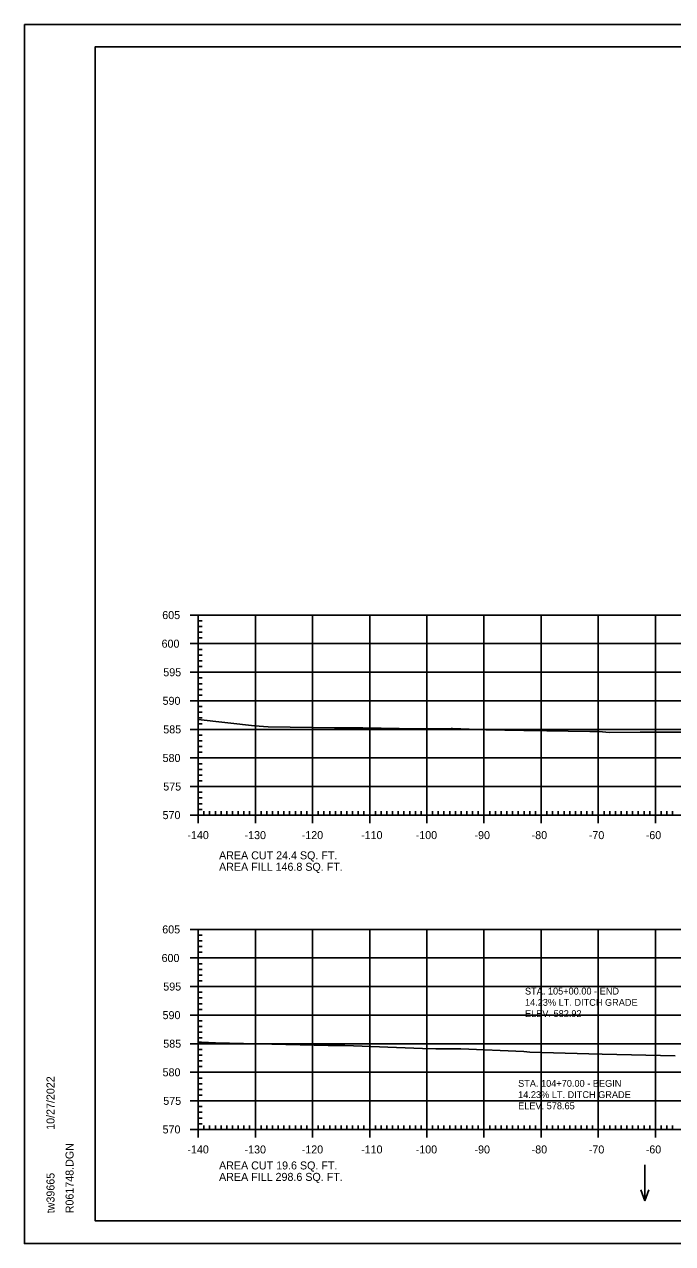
# Model space of a CAD drawing. Extents: x 961436 to 1372525, y 380079 to 2027791.
# Drawn here: x 1371024.5 to 1371137.9, y 380535.8 to 380749.1 of the extents above; entities that cross this region are included whole.
import ezdxf

# ---------------------------------------------------------------- set-up
doc = ezdxf.new("R2010")
doc.units = 0
for name, color, linetype in [('R_Axis', 7, 'Continuous'), ('R_Axis Annot', 7, 'Continuous'), ('R_Border', 7, 'Continuous'), ('R_Exist Surface', 7, 'Continuous'), ('R_Fin Surface Annot', 7, 'Continuous'), ('R_Grid', 7, 'Continuous'), ('R_No Plot', 7, 'Continuous'), ('R_Water Annot', 7, 'Continuous')]:
    doc.layers.add(name, color=color, linetype=linetype)

msp = doc.modelspace()

# ---------------------------------------------------------------- linework, layer by layer
at = {"layer": 'R_Axis'}
for p, q in [((1371053.48, 380645.73), (1371056.28, 380645.73)), ((1371054.88, 380610.73), (1371054.88, 380645.73)), ((1371054.88, 380644.73), (1371055.58, 380644.73)), ((1371054.88, 380643.73), (1371055.58, 380643.73)), ((1371054.88, 380642.73), (1371055.58, 380642.73)), ((1371054.88, 380641.73), (1371055.58, 380641.73)), ((1371053.48, 380640.73), (1371056.28, 380640.73)), ((1371054.88, 380639.73), (1371055.58, 380639.73)), ((1371054.88, 380638.73), (1371055.58, 380638.73)), ((1371054.88, 380637.73), (1371055.58, 380637.73)), ((1371053.48, 380635.73), (1371056.28, 380635.73)), ((1371054.88, 380636.73), (1371055.58, 380636.73)), ((1371054.88, 380634.73), (1371055.58, 380634.73)), ((1371054.88, 380633.73), (1371055.58, 380633.73)), ((1371054.88, 380632.73), (1371055.58, 380632.73)), ((1371053.48, 380630.73), (1371056.28, 380630.73)), ((1371054.88, 380631.73), (1371055.58, 380631.73)), ((1371054.88, 380629.73), (1371055.58, 380629.73)), ((1371054.88, 380628.73), (1371055.58, 380628.73)), ((1371054.88, 380627.73), (1371055.58, 380627.73)), ((1371054.88, 380626.73), (1371055.58, 380626.73)), ((1371053.48, 380625.73), (1371056.28, 380625.73)), ((1371054.88, 380624.73), (1371055.58, 380624.73)), ((1371054.88, 380623.73), (1371055.58, 380623.73)), ((1371054.88, 380622.73), (1371055.58, 380622.73)), ((1371053.48, 380620.73), (1371056.28, 380620.73)), ((1371054.88, 380621.73), (1371055.58, 380621.73)), ((1371054.88, 380619.73), (1371055.58, 380619.73)), ((1371054.88, 380618.73), (1371055.58, 380618.73)), ((1371053.48, 380615.73), (1371056.28, 380615.73)), ((1371054.88, 380617.73), (1371055.58, 380617.73)), ((1371054.88, 380616.73), (1371055.58, 380616.73)), ((1371054.88, 380614.73), (1371055.58, 380614.73)), ((1371054.88, 380613.73), (1371055.58, 380613.73)), ((1371054.88, 380612.73), (1371055.58, 380612.73)), ((1371054.88, 380609.33), (1371054.88, 380612.13)), ((1371054.88, 380611.73), (1371055.58, 380611.73)), ((1371055.88, 380610.73), (1371055.88, 380611.43)), ((1371056.88, 380610.73), (1371056.88, 380611.43)), ((1371057.88, 380610.73), (1371057.88, 380611.43)), ((1371058.88, 380610.73), (1371058.88, 380611.43)), ((1371059.88, 380610.73), (1371059.88, 380611.43)), ((1371060.88, 380610.73), (1371060.88, 380611.43)), ((1371061.88, 380610.73), (1371061.88, 380611.43)), ((1371062.88, 380610.73), (1371062.88, 380611.43)), ((1371063.88, 380610.73), (1371063.88, 380611.43)), ((1371064.88, 380609.33), (1371064.88, 380612.13)), ((1371065.88, 380610.73), (1371065.88, 380611.43)), ((1371066.88, 380610.73), (1371066.88, 380611.43)), ((1371067.88, 380610.73), (1371067.88, 380611.43)), ((1371068.88, 380610.73), (1371068.88, 380611.43)), ((1371069.88, 380610.73), (1371069.88, 380611.43)), ((1371070.88, 380610.73), (1371070.88, 380611.43)), ((1371071.88, 380610.73), (1371071.88, 380611.43)), ((1371072.88, 380610.73), (1371072.88, 380611.43)), ((1371073.88, 380610.73), (1371073.88, 380611.43)), ((1371074.88, 380609.33), (1371074.88, 380612.13)), ((1371075.88, 380610.73), (1371075.88, 380611.43)), ((1371076.88, 380610.73), (1371076.88, 380611.43)), ((1371077.88, 380610.73), (1371077.88, 380611.43)), ((1371078.88, 380610.73), (1371078.88, 380611.43)), ((1371079.88, 380610.73), (1371079.88, 380611.43)), ((1371080.88, 380610.73), (1371080.88, 380611.43)), ((1371081.88, 380610.73), (1371081.88, 380611.43)), ((1371082.88, 380610.73), (1371082.88, 380611.43)), ((1371083.88, 380610.73), (1371083.88, 380611.43)), ((1371084.88, 380609.33), (1371084.88, 380612.13)), ((1371085.88, 380610.73), (1371085.88, 380611.43)), ((1371086.88, 380610.73), (1371086.88, 380611.43)), ((1371087.88, 380610.73), (1371087.88, 380611.43)), ((1371088.88, 380610.73), (1371088.88, 380611.43)), ((1371089.88, 380610.73), (1371089.88, 380611.43)), ((1371090.88, 380610.73), (1371090.88, 380611.43)), ((1371091.88, 380610.73), (1371091.88, 380611.43)), ((1371092.88, 380610.73), (1371092.88, 380611.43)), ((1371093.88, 380610.73), (1371093.88, 380611.43)), ((1371094.88, 380609.33), (1371094.88, 380612.13)), ((1371095.88, 380610.73), (1371095.88, 380611.43)), ((1371096.88, 380610.73), (1371096.88, 380611.43)), ((1371097.88, 380610.73), (1371097.88, 380611.43)), ((1371098.88, 380610.73), (1371098.88, 380611.43)), ((1371099.88, 380610.73), (1371099.88, 380611.43)), ((1371100.88, 380610.73), (1371100.88, 380611.43)), ((1371101.88, 380610.73), (1371101.88, 380611.43)), ((1371102.88, 380610.73), (1371102.88, 380611.43)), ((1371103.88, 380610.73), (1371103.88, 380611.43)), ((1371104.88, 380609.33), (1371104.88, 380612.13)), ((1371105.88, 380610.73), (1371105.88, 380611.43)), ((1371106.88, 380610.73), (1371106.88, 380611.43)), ((1371107.88, 380610.73), (1371107.88, 380611.43)), ((1371108.88, 380610.73), (1371108.88, 380611.43)), ((1371109.88, 380610.73), (1371109.88, 380611.43)), ((1371110.88, 380610.73), (1371110.88, 380611.43)), ((1371111.88, 380610.73), (1371111.88, 380611.43)), ((1371112.88, 380610.73), (1371112.88, 380611.43)), ((1371113.88, 380610.73), (1371113.88, 380611.43)), ((1371114.88, 380609.33), (1371114.88, 380612.13)), ((1371115.88, 380610.73), (1371115.88, 380611.43)), ((1371116.88, 380610.73), (1371116.88, 380611.43)), ((1371117.88, 380610.73), (1371117.88, 380611.43)), ((1371118.88, 380610.73), (1371118.88, 380611.43)), ((1371119.88, 380610.73), (1371119.88, 380611.43)), ((1371120.88, 380610.73), (1371120.88, 380611.43)), ((1371121.88, 380610.73), (1371121.88, 380611.43)), ((1371122.88, 380610.73), (1371122.88, 380611.43)), ((1371123.88, 380610.73), (1371123.88, 380611.43)), ((1371124.88, 380609.33), (1371124.88, 380612.13)), ((1371125.88, 380610.73), (1371125.88, 380611.43)), ((1371126.88, 380610.73), (1371126.88, 380611.43)), ((1371127.88, 380610.73), (1371127.88, 380611.43)), ((1371128.88, 380610.73), (1371128.88, 380611.43)), ((1371129.88, 380610.73), (1371129.88, 380611.43)), ((1371130.88, 380610.73), (1371130.88, 380611.43)), ((1371131.88, 380610.73), (1371131.88, 380611.43)), ((1371132.88, 380610.73), (1371132.88, 380611.43)), ((1371133.88, 380610.73), (1371133.88, 380611.43)), ((1371134.88, 380609.33), (1371134.88, 380612.13)), ((1371135.88, 380610.73), (1371135.88, 380611.43)), ((1371136.88, 380610.73), (1371136.88, 380611.43)), ((1371137.88, 380610.73), (1371137.88, 380611.43)), ((1371053.48, 380610.73), (1371056.28, 380610.73)), ((1371054.88, 380610.73), (1371334.88, 380610.73)), ((1371053.48, 380590.73), (1371056.28, 380590.73)), ((1371054.88, 380555.73), (1371054.88, 380590.73)), ((1371054.88, 380589.73), (1371055.58, 380589.73)), ((1371054.88, 380588.73), (1371055.58, 380588.73)), ((1371054.88, 380587.73), (1371055.58, 380587.73)), ((1371054.88, 380586.73), (1371055.58, 380586.73)), ((1371053.48, 380585.73), (1371056.28, 380585.73)), ((1371054.88, 380584.73), (1371055.58, 380584.73)), ((1371054.88, 380583.73), (1371055.58, 380583.73)), ((1371054.88, 380582.73), (1371055.58, 380582.73)), ((1371054.88, 380581.73), (1371055.58, 380581.73)), ((1371053.48, 380580.73), (1371056.28, 380580.73)), ((1371054.88, 380579.73), (1371055.58, 380579.73)), ((1371054.88, 380578.73), (1371055.58, 380578.73)), ((1371054.88, 380577.73), (1371055.58, 380577.73)), ((1371053.48, 380575.73), (1371056.28, 380575.73)), ((1371054.88, 380576.73), (1371055.58, 380576.73)), ((1371054.88, 380574.73), (1371055.58, 380574.73)), ((1371054.88, 380573.73), (1371055.58, 380573.73)), ((1371054.88, 380572.73), (1371055.58, 380572.73)), ((1371054.88, 380571.73), (1371055.58, 380571.73)), ((1371053.48, 380570.73), (1371056.28, 380570.73)), ((1371054.88, 380569.73), (1371055.58, 380569.73)), ((1371054.88, 380568.73), (1371055.58, 380568.73)), ((1371054.88, 380567.73), (1371055.58, 380567.73)), ((1371054.88, 380566.73), (1371055.58, 380566.73)), ((1371053.48, 380565.73), (1371056.28, 380565.73)), ((1371054.88, 380564.73), (1371055.58, 380564.73)), ((1371054.88, 380563.73), (1371055.58, 380563.73)), ((1371054.88, 380562.73), (1371055.58, 380562.73)), ((1371053.48, 380560.73), (1371056.28, 380560.73)), ((1371054.88, 380561.73), (1371055.58, 380561.73)), ((1371054.88, 380559.73), (1371055.58, 380559.73)), ((1371054.88, 380558.73), (1371055.58, 380558.73)), ((1371054.88, 380557.73), (1371055.58, 380557.73)), ((1371054.88, 380554.33), (1371054.88, 380557.13)), ((1371054.88, 380556.73), (1371055.58, 380556.73)), ((1371055.88, 380555.73), (1371055.88, 380556.43)), ((1371056.88, 380555.73), (1371056.88, 380556.43)), ((1371057.88, 380555.73), (1371057.88, 380556.43)), ((1371058.88, 380555.73), (1371058.88, 380556.43)), ((1371059.88, 380555.73), (1371059.88, 380556.43)), ((1371060.88, 380555.73), (1371060.88, 380556.43)), ((1371061.88, 380555.73), (1371061.88, 380556.43)), ((1371062.88, 380555.73), (1371062.88, 380556.43)), ((1371063.88, 380555.73), (1371063.88, 380556.43)), ((1371064.88, 380554.33), (1371064.88, 380557.13)), ((1371065.88, 380555.73), (1371065.88, 380556.43)), ((1371066.88, 380555.73), (1371066.88, 380556.43)), ((1371067.88, 380555.73), (1371067.88, 380556.43)), ((1371068.88, 380555.73), (1371068.88, 380556.43)), ((1371069.88, 380555.73), (1371069.88, 380556.43)), ((1371070.88, 380555.73), (1371070.88, 380556.43)), ((1371071.88, 380555.73), (1371071.88, 380556.43)), ((1371072.88, 380555.73), (1371072.88, 380556.43)), ((1371073.88, 380555.73), (1371073.88, 380556.43)), ((1371074.88, 380554.33), (1371074.88, 380557.13)), ((1371075.88, 380555.73), (1371075.88, 380556.43)), ((1371076.88, 380555.73), (1371076.88, 380556.43)), ((1371077.88, 380555.73), (1371077.88, 380556.43)), ((1371078.88, 380555.73), (1371078.88, 380556.43)), ((1371079.88, 380555.73), (1371079.88, 380556.43)), ((1371080.88, 380555.73), (1371080.88, 380556.43)), ((1371081.88, 380555.73), (1371081.88, 380556.43)), ((1371082.88, 380555.73), (1371082.88, 380556.43)), ((1371083.88, 380555.73), (1371083.88, 380556.43)), ((1371084.88, 380554.33), (1371084.88, 380557.13)), ((1371085.88, 380555.73), (1371085.88, 380556.43)), ((1371086.88, 380555.73), (1371086.88, 380556.43)), ((1371087.88, 380555.73), (1371087.88, 380556.43)), ((1371088.88, 380555.73), (1371088.88, 380556.43)), ((1371089.88, 380555.73), (1371089.88, 380556.43)), ((1371090.88, 380555.73), (1371090.88, 380556.43)), ((1371091.88, 380555.73), (1371091.88, 380556.43)), ((1371092.88, 380555.73), (1371092.88, 380556.43)), ((1371093.88, 380555.73), (1371093.88, 380556.43)), ((1371094.88, 380554.33), (1371094.88, 380557.13)), ((1371095.88, 380555.73), (1371095.88, 380556.43)), ((1371096.88, 380555.73), (1371096.88, 380556.43)), ((1371097.88, 380555.73), (1371097.88, 380556.43)), ((1371098.88, 380555.73), (1371098.88, 380556.43)), ((1371099.88, 380555.73), (1371099.88, 380556.43)), ((1371100.88, 380555.73), (1371100.88, 380556.43)), ((1371101.88, 380555.73), (1371101.88, 380556.43)), ((1371102.88, 380555.73), (1371102.88, 380556.43)), ((1371103.88, 380555.73), (1371103.88, 380556.43)), ((1371104.88, 380554.33), (1371104.88, 380557.13)), ((1371105.88, 380555.73), (1371105.88, 380556.43)), ((1371106.88, 380555.73), (1371106.88, 380556.43)), ((1371107.88, 380555.73), (1371107.88, 380556.43)), ((1371108.88, 380555.73), (1371108.88, 380556.43)), ((1371109.88, 380555.73), (1371109.88, 380556.43)), ((1371110.88, 380555.73), (1371110.88, 380556.43)), ((1371111.88, 380555.73), (1371111.88, 380556.43)), ((1371112.88, 380555.73), (1371112.88, 380556.43)), ((1371113.88, 380555.73), (1371113.88, 380556.43)), ((1371114.88, 380554.33), (1371114.88, 380557.13)), ((1371115.88, 380555.73), (1371115.88, 380556.43)), ((1371116.88, 380555.73), (1371116.88, 380556.43)), ((1371117.88, 380555.73), (1371117.88, 380556.43)), ((1371118.88, 380555.73), (1371118.88, 380556.43)), ((1371119.88, 380555.73), (1371119.88, 380556.43)), ((1371120.88, 380555.73), (1371120.88, 380556.43)), ((1371121.88, 380555.73), (1371121.88, 380556.43)), ((1371122.88, 380555.73), (1371122.88, 380556.43)), ((1371123.88, 380555.73), (1371123.88, 380556.43)), ((1371124.88, 380554.33), (1371124.88, 380557.13)), ((1371125.88, 380555.73), (1371125.88, 380556.43)), ((1371126.88, 380555.73), (1371126.88, 380556.43)), ((1371127.88, 380555.73), (1371127.88, 380556.43)), ((1371128.88, 380555.73), (1371128.88, 380556.43)), ((1371129.88, 380555.73), (1371129.88, 380556.43)), ((1371130.88, 380555.73), (1371130.88, 380556.43)), ((1371131.88, 380555.73), (1371131.88, 380556.43)), ((1371132.88, 380555.73), (1371132.88, 380556.43)), ((1371133.88, 380555.73), (1371133.88, 380556.43)), ((1371134.88, 380554.33), (1371134.88, 380557.13)), ((1371135.88, 380555.73), (1371135.88, 380556.43)), ((1371136.88, 380555.73), (1371136.88, 380556.43)), ((1371137.88, 380555.73), (1371137.88, 380556.43)), ((1371053.48, 380555.73), (1371056.28, 380555.73)), ((1371054.88, 380555.73), (1371334.88, 380555.73))]:
    msp.add_line(p, q, dxfattribs=at)
at = {"layer": 'R_Border'}
for p, q in [((1371036.88, 380745.19), (1371353.06, 380745.19)), ((1371036.88, 380539.73), (1371036.88, 380745.19)), ((1371036.88, 380539.73), (1371036.88, 380539.73)), ((1371353.06, 380539.73), (1371036.88, 380539.73))]:
    msp.add_line(p, q, dxfattribs=at)
at = {"layer": 'R_Exist Surface'}
for points in [[(1371054.88, 380627.45), (1371064.74, 380626.36), (1371067.12, 380626.17), (1371078.72, 380626.01), (1371083.4, 380625.99), (1371083.7, 380625.98), (1371093.22, 380625.82), (1371099.16, 380625.9), (1371099.34, 380625.88), (1371105.21, 380625.65), (1371111.85, 380625.53), (1371112.09, 380625.54), (1371123.4, 380625.37), (1371125.01, 380625.35), (1371126.8, 380625.21), (1371132.19, 380625.24), (1371140.02, 380625.23)], [(1371054.88, 380571.01), (1371055.44, 380571.01), (1371057.89, 380570.91), (1371077.64, 380570.41), (1371080.54, 380570.41), (1371094.14, 380569.88), (1371096.48, 380569.85), (1371100.8, 380569.82), (1371111.84, 380569.37), (1371112.91, 380569.24), (1371123.21, 380568.98), (1371125.57, 380568.88), (1371138.34, 380568.59)]]:
    msp.add_lwpolyline(points, dxfattribs=at)
at = {"layer": 'R_Grid'}
for p, q in [((1371054.88, 380645.73), (1371334.88, 380645.73)), ((1371054.88, 380610.73), (1371054.88, 380645.73)), ((1371064.88, 380610.73), (1371064.88, 380645.73)), ((1371074.88, 380610.73), (1371074.88, 380645.73)), ((1371084.88, 380610.73), (1371084.88, 380645.73)), ((1371094.88, 380610.73), (1371094.88, 380645.73)), ((1371104.88, 380610.73), (1371104.88, 380645.73)), ((1371114.88, 380610.73), (1371114.88, 380645.73)), ((1371124.88, 380610.73), (1371124.88, 380645.73)), ((1371134.88, 380610.73), (1371134.88, 380645.73)), ((1371054.88, 380640.73), (1371334.88, 380640.73)), ((1371054.88, 380635.73), (1371334.88, 380635.73)), ((1371054.88, 380630.73), (1371334.88, 380630.73)), ((1371054.88, 380625.73), (1371334.88, 380625.73)), ((1371054.88, 380620.73), (1371334.88, 380620.73)), ((1371054.88, 380615.73), (1371334.88, 380615.73)), ((1371054.88, 380610.73), (1371334.88, 380610.73)), ((1371054.88, 380590.73), (1371334.88, 380590.73)), ((1371054.88, 380555.73), (1371054.88, 380590.73)), ((1371064.88, 380555.73), (1371064.88, 380590.73)), ((1371074.88, 380555.73), (1371074.88, 380590.73)), ((1371084.88, 380555.73), (1371084.88, 380590.73)), ((1371094.88, 380555.73), (1371094.88, 380590.73)), ((1371104.88, 380555.73), (1371104.88, 380590.73)), ((1371114.88, 380555.73), (1371114.88, 380590.73)), ((1371124.88, 380555.73), (1371124.88, 380590.73)), ((1371134.88, 380555.73), (1371134.88, 380590.73)), ((1371054.88, 380585.73), (1371334.88, 380585.73)), ((1371054.88, 380580.73), (1371334.88, 380580.73)), ((1371054.88, 380575.73), (1371334.88, 380575.73)), ((1371054.88, 380570.73), (1371334.88, 380570.73)), ((1371054.88, 380565.73), (1371334.88, 380565.73)), ((1371054.88, 380560.73), (1371334.88, 380560.73)), ((1371054.88, 380555.73), (1371334.88, 380555.73))]:
    msp.add_line(p, q, dxfattribs=at)
at = {"layer": 'R_No Plot'}
for p, q in [((1371024.48, 380749.09), (1371357.81, 380749.09)), ((1371024.48, 380535.76), (1371357.81, 380535.76))]:
    msp.add_line(p, q, dxfattribs=at)
for points in [[(1371024.47, 380749.09), (1371357.81, 380749.09), (1371357.81, 380535.75), (1371024.47, 380535.75)], [(1371270.8, 380745.19), (1371290.42, 380745.19), (1371290.42, 380735.31), (1371306.53, 380735.31), (1371329.73, 380735.31), (1371329.85, 380707.16), (1371353.06, 380707.16), (1371353.06, 380539.73), (1371036.88, 380539.73), (1371036.88, 380745.19)]]:
    msp.add_lwpolyline(points, close=True, dxfattribs=at)
at = {"layer": 'R_Water Annot'}
for p, q in [((1371133.01, 380549.54), (1371133.01, 380543.26)), ((1371133.01, 380543.26), (1371132.31, 380545.18)), ((1371133.01, 380543.26), (1371133.71, 380545.18))]:
    msp.add_line(p, q, dxfattribs=at)

# ---------------------------------------------------------------- texts
at = {"layer": 'R_Axis Annot'}
for s, p in [('605', (1371048.59, 380645.03)), ('600', (1371048.47, 380640.03)), ('595', (1371048.77, 380635.03)), ('590', (1371048.65, 380630.03)), ('585', (1371048.77, 380625.03)), ('580', (1371048.65, 380620.03)), ('575', (1371048.77, 380615.03)), ('570', (1371048.65, 380610.03)), ('-140', (1371052.99, 380606.53)), ('-130', (1371062.99, 380606.53)), ('-120', (1371072.99, 380606.53)), ('-110', (1371083.38, 380606.53)), ('-100', (1371092.93, 380606.53)), ('-90', (1371103.22, 380606.53)), ('-80', (1371113.22, 380606.53)), ('-70', (1371123.22, 380606.53)), ('-60', (1371133.18, 380606.53)), ('AREA CUT 24.4 SQ. FT.', (1371058.53, 380602.99)), ('AREA FILL 146.8 SQ. FT.', (1371058.53, 380600.99)), ('605', (1371048.59, 380590.03)), ('600', (1371048.47, 380585.03)), ('595', (1371048.77, 380580.03)), ('590', (1371048.65, 380575.03)), ('585', (1371048.77, 380570.03)), ('580', (1371048.65, 380565.03)), ('575', (1371048.77, 380560.03)), ('570', (1371048.65, 380555.03)), ('-140', (1371052.99, 380551.53)), ('-130', (1371062.99, 380551.53)), ('-120', (1371072.99, 380551.53)), ('-110', (1371083.38, 380551.53)), ('-100', (1371092.93, 380551.53)), ('-90', (1371103.22, 380551.53)), ('-80', (1371113.22, 380551.53)), ('-70', (1371123.22, 380551.53)), ('-60', (1371133.18, 380551.53)), ('AREA CUT 19.6 SQ. FT.', (1371058.53, 380548.73)), ('AREA FILL 298.6 SQ. FT.', (1371058.53, 380546.73))]:
    msp.add_text(s, height=1.4, dxfattribs=at).set_placement(p)
at = {"layer": 'R_Border'}
for s, p in [('10/27/2022', (1371029.74, 380555.66)), ('R061748.DGN', (1371033.07, 380541.06)), ('tw39665', (1371029.74, 380541.06))]:
    msp.add_text(s, height=1.4, rotation=90, dxfattribs=at).set_placement(p)
at = {"layer": 'R_Fin Surface Annot'}
for s, p in [('STA. 105+00.00 - END', (1371112.05, 380579.33)), ('14.23% LT. DITCH GRADE', (1371112.05, 380577.36)), ('ELEV. 582.92', (1371112.05, 380575.4)), ('STA. 104+70.00 - BEGIN', (1371110.85, 380563.19)), ('14.23% LT. DITCH GRADE', (1371110.85, 380561.22)), ('ELEV. 578.65', (1371110.85, 380559.26))]:
    msp.add_text(s, height=1.2, dxfattribs=at).set_placement(p)

doc.saveas('drawing.dxf')
